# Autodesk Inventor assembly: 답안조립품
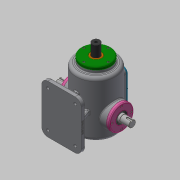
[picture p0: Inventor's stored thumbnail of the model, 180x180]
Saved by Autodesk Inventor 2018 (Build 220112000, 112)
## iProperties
Created: 2021-11
Part Number: 답안조립품
Material: 일반
Document SubType Name: Assembly
Designer: home
Author: home
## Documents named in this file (14)
- C:\Users\home\Desktop\711106V1039 (1)\답안조립품.iam
- C:\Users\home\Desktop\711106V1039 (1)\본체.ipt
- C:\Users\home\Desktop\711106V1039 (1)\베어링 6205.ipt
- 베어링 6205.ipt
- C:\Users\home\Desktop\711106V1039 (1)\볼트 M4x0.7.ipt
- C:\Users\home\Desktop\711106V1039 (1)\부시.ipt
- C:\Users\home\Desktop\711106V1039 (1)\상부커버.ipt
- C:\Users\home\Desktop\711106V1039 (1)\슬라이드 커버.ipt
- C:\Users\home\Desktop\711106V1039 (1)\슬라이드.ipt
- C:\Users\home\Desktop\711106V1039 (1)\오일실.ipt
- 오일실.ipt
- C:\Users\home\Desktop\711106V1039 (1)\육각머리볼트 M4.ipt
- C:\Users\home\Desktop\711106V1039 (1)\축 커버.ipt
- C:\Users\home\Desktop\711106V1039 (1)\편심축.ipt
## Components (12 placed, 1 different names)
1. M4x0.7:1
2. M4x0.7:3
3. M4x0.7:4
4. M4x0.7:5
5. M4x0.7:7
6. M4x0.7:8
7. M4x0.7:9
8. M4x0.7:10
9. M4x0.7:6
10. M4x0.7:11
11. M4x0.7:12
12. M4x0.7:13
